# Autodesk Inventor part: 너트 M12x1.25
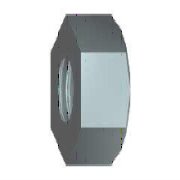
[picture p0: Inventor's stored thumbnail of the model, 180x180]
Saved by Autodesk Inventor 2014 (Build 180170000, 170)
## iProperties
IsCustomPart: 0
Created: 2015-12
Part Number: 너트 M12x1.25
Material: 스테인리스강
Description: 6각 너트
Document SubType Name: Modeling
Standard: KS B 1012
Designer: mdu
Standards Organization: KS
Language: ko-KR
Size Designation: M12x1.25
Categories: <MemberInstance><Categories><Category DisplayName="조임쇠" InternalName="e4da775c-781d-43d5-af7c-5136215cf5a6" Mnemonic="FSTN"><Category DisplayName="너트" InternalN
Density: 8.08 g/cm^3
Appearance: 반광택
Author: mdu
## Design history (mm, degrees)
sketch "스케치1"
  geometry: L1 (10.97, 0)-(5.485, -9.5); L2 (5.485, -9.5)-(-5.485, -9.5); L3 (-5.485, -9.5)-(-10.97, 0); L4 (-10.97, 0)-(-5.485, 9.5); L5 (-5.485, 9.5)-(5.485, 9.5); L6 (5.485, 9.5)-(10.97, 0); 2 further points
  constraints: 12 end point, 1 coincident, 1 horizontal, 11 other
  dimensions: "d0" = 21.93931 distance of L1.start L3.end (= 1.1547 x SW)
extrude "본체" new body sketch "스케치1" distance "d1" = 10 (= KOH); taper "d2" = 0 deg
sketch "스케치2"
  geometry: 1 further point
hole "스레드" sketch "스케치2" diameter "d6" = 10.647; stored, may be unused: countersink angle "d10" = 82 deg, drill point angle "d12" = 118 deg; dims "d7" = 12.7, "d8" = 9.525, "d9" = 6.35, "d11" = 19.05
sketch "스케치3"
  geometry: L1 (0, 10.97)-(10, 10.97) reference; L2 (10, 5.485)-(10, 10.97) reference; L3 (-2, 0)-(12, 0) reference; L4 (9.151, 10.97)-(10, 9.5)
  constraints: 2 end point, 2 point on line
  dimensions: "d3" = 19 diameter of L4.end L3 (= SW01); "d4" = 30 deg angle of L2 L4 (= ANG2)
revolve "모따기3" sketch "스케치3" stored, may be unused: angle "d5" = 90 deg
workaxis "Work Axis1"
workplane "Work Plane1"
body "Solid1"
chamfer "모따기1" distance "d13" = 0.67658 (= -0.5 x GD1 + 0.5 x NND); stored, may be unused: angle "d14" = 30 deg, second distance "d21" = 0.67658 (= -0.5 x GD1 + 0.5 x NND)
chamfer "모따기2" distance "d15" = 0.67658 (= -0.5 x GD1 + 0.5 x NND); stored, may be unused: angle "d16" = 30 deg, second distance "d22" = 0.67658 (= -0.5 x GD1 + 0.5 x NND)
other parameters: "ANG2" = 30 deg [user parameter; used in 1 equation term], "NND" = 12 [user parameter; used in 4 equation terms], "KOH" = 10 [user parameter; used in 1 equation term], "SW" = 19 [user parameter; used in 3 equation terms], "SW01" = 19 (= SW) [user parameter; used in 1 equation term], "GD1" = 10.64684 (computed from THREADDIA, PTC, TOA) [user parameter; used in 4 equation terms], "d19" = 0, "d20" = 0, "d24" = 0, "d25" = 0, "GUL" = 0.67658 (= 0.541266 x PTC) [user parameter], "TPU" = 8 (computed from PTC) [user parameter], "TOA" = 30 deg [user parameter; used in 1 equation term], "PTC" = 1.25 [user parameter; used in 4 equation terms], "E0" = 21.945 (= 1.155 x SW) [user parameter], "THREADDIA" = 12 [user parameter; used in 1 equation term], "GAL" = 0.67658 (= 0.541266 x PTC) [user parameter]
